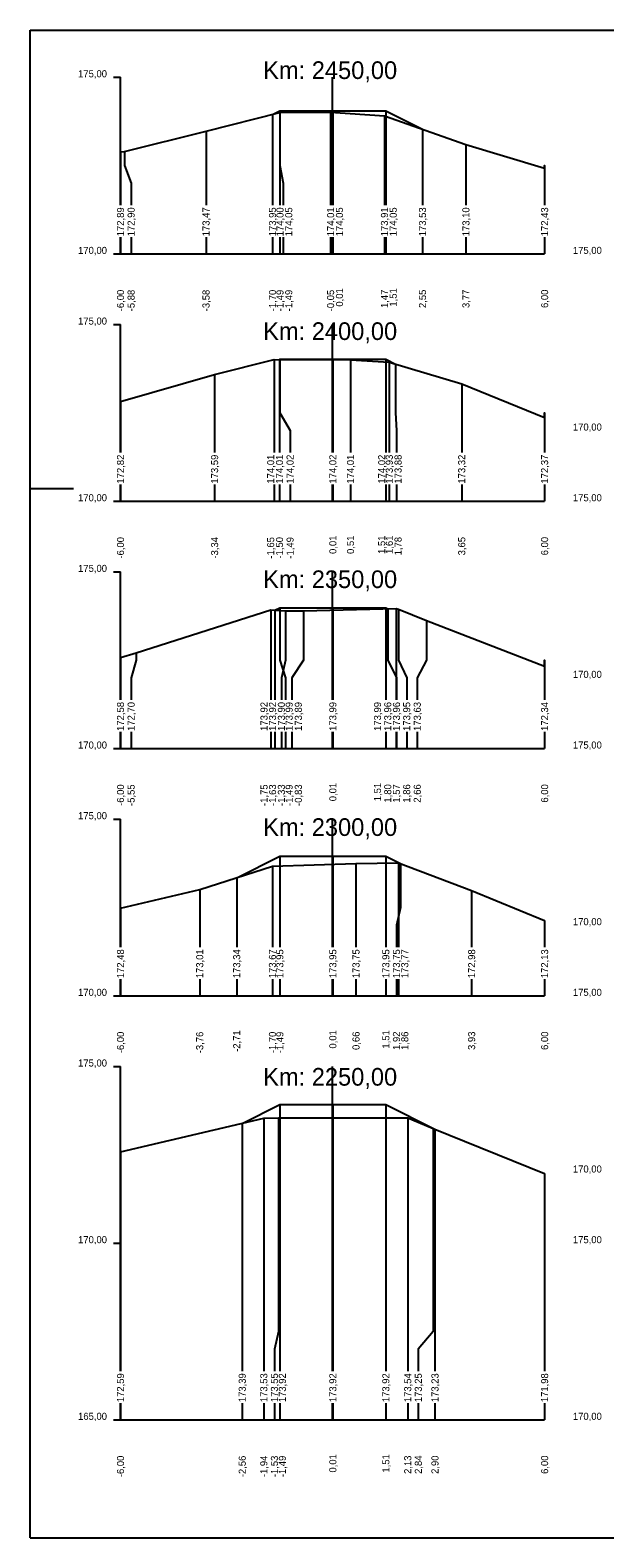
# Model space of a CAD drawing. Extents: x -614174 to -599765, y -1185887 to -1181080.
# Drawn here: x -601090.94 to -601074.69, y -1184533.61 to -1184490.94 of the extents above; entities that cross this region are included whole.
import ezdxf

# ---------------------------------------------------------------- set-up
doc = ezdxf.new("R2010")
doc.units = 0
for name, color, linetype in [('11', 7, 'Continuous'), ('16', 7, 'Continuous'), ('21', 7, 'Continuous'), ('28', 7, 'Continuous'), ('59', 7, 'Continuous'), ('8', 7, 'Continuous'), ('návrh', 7, 'Continuous')]:
    doc.layers.add(name, color=color, linetype=linetype)

msp = doc.modelspace()

# ---------------------------------------------------------------- linework, layer by layer
for points in [[(-601088.389, -1184494.376), (-601088.271, -1184494.371), (-601085.969, -1184493.797), (-601083.876, -1184493.271), (-601082.444, -1184493.262), (-601080.921, -1184493.362), (-601078.615, -1184494.169), (-601076.389, -1184494.844)], [(-601084.088, -1184493.324), (-601084.088, -1184493.324), (-601084.089, -1184493.324)], [(-601084.088, -1184493.324), (-601083.881, -1184493.22), (-601082.381, -1184493.22), (-601080.881, -1184493.22), (-601079.844, -1184493.739)], [(-601083.881, -1184493.22), (-601083.881, -1184493.22), (-601083.881, -1184493.22)], [(-601082.381, -1184493.22), (-601082.381, -1184493.22), (-601082.381, -1184493.22)], [(-601080.881, -1184493.22), (-601080.881, -1184493.22), (-601080.881, -1184493.22)], [(-601088.389, -1184501.448), (-601085.726, -1184500.681), (-601084.043, -1184500.257), (-601081.882, -1184500.263), (-601080.784, -1184500.336), (-601078.735, -1184500.949), (-601076.389, -1184501.899)], [(-601083.891, -1184500.257), (-601083.881, -1184500.252), (-601082.381, -1184500.252), (-601080.881, -1184500.252), (-601080.61, -1184500.387)], [(-601083.891, -1184500.257), (-601083.891, -1184500.257), (-601083.891, -1184500.257)], [(-601083.881, -1184500.252), (-601083.881, -1184500.252), (-601083.881, -1184500.252)], [(-601082.381, -1184500.252), (-601082.381, -1184500.252), (-601082.381, -1184500.252)], [(-601080.881, -1184500.252), (-601080.881, -1184500.252), (-601080.881, -1184500.252)], [(-601088.389, -1184508.694), (-601087.941, -1184508.565), (-601084.137, -1184507.347), (-601083.717, -1184507.374), (-601083.215, -1184507.375), (-601080.592, -1184507.308), (-601080.525, -1184507.324), (-601079.733, -1184507.644), (-601076.389, -1184508.934)], [(-601084.022, -1184507.354), (-601083.881, -1184507.284), (-601082.381, -1184507.284), (-601080.881, -1184507.284), (-601080.821, -1184507.314)], [(-601084.022, -1184507.354), (-601084.022, -1184507.354), (-601084.022, -1184507.354)], [(-601083.881, -1184507.284), (-601083.881, -1184507.284), (-601083.881, -1184507.284)], [(-601082.381, -1184507.284), (-601082.381, -1184507.284), (-601082.381, -1184507.284)], [(-601080.881, -1184507.284), (-601080.881, -1184507.284), (-601080.881, -1184507.284)], [(-601085.101, -1184514.926), (-601083.881, -1184514.316), (-601082.381, -1184514.316), (-601080.881, -1184514.316), (-601080.471, -1184514.521)], [(-601083.881, -1184514.316), (-601083.881, -1184514.316), (-601083.881, -1184514.316)], [(-601082.381, -1184514.316), (-601082.381, -1184514.316), (-601082.381, -1184514.316)], [(-601080.881, -1184514.316), (-601080.881, -1184514.316), (-601080.881, -1184514.316)], [(-601088.389, -1184515.79), (-601086.148, -1184515.26), (-601084.09, -1184514.603), (-601081.726, -1184514.522), (-601080.526, -1184514.5), (-601078.454, -1184515.285), (-601076.389, -1184516.14)], [(-601085.102, -1184514.926), (-601085.101, -1184514.926), (-601085.101, -1184514.925)], [(-601084.944, -1184521.879), (-601083.881, -1184521.348), (-601082.381, -1184521.348), (-601080.881, -1184521.348), (-601079.491, -1184522.043)], [(-601083.881, -1184521.348), (-601083.881, -1184521.348), (-601083.881, -1184521.348)], [(-601082.381, -1184521.348), (-601082.381, -1184521.348), (-601082.381, -1184521.348)], [(-601080.881, -1184521.348), (-601080.881, -1184521.348), (-601080.881, -1184521.348)], [(-601088.389, -1184522.684), (-601084.334, -1184521.736), (-601083.915, -1184521.722), (-601080.262, -1184521.726), (-601079.546, -1184522.021), (-601076.389, -1184523.294)], [(-601084.944, -1184521.879), (-601084.944, -1184521.879), (-601084.944, -1184521.879)]]:
    msp.add_lwpolyline(points)
at = {"layer": '11'}
for points in [[(-601084.088, -1184493.324), (-601084.088, -1184494.77), (-601084.088, -1184495.27), (-601084.088, -1184495.892)], [(-601083.881, -1184493.22), (-601083.881, -1184494.77), (-601083.788, -1184495.27), (-601083.788, -1184495.892)], [(-601083.876, -1184493.271), (-601083.876, -1184494.77), (-601083.876, -1184495.27), (-601083.876, -1184495.892)], [(-601082.444, -1184493.262), (-601082.444, -1184494.77), (-601082.444, -1184495.27), (-601082.444, -1184495.892)], [(-601082.381, -1184493.22), (-601082.381, -1184494.77), (-601082.381, -1184495.27), (-601082.381, -1184495.892)], [(-601080.921, -1184493.362), (-601080.921, -1184494.77), (-601080.921, -1184495.27), (-601080.921, -1184495.892)], [(-601080.881, -1184493.22), (-601080.881, -1184494.77), (-601080.881, -1184495.27), (-601080.881, -1184495.892)], [(-601085.969, -1184493.797), (-601085.969, -1184494.77), (-601085.969, -1184495.27), (-601085.969, -1184495.892)], [(-601079.844, -1184493.739), (-601079.844, -1184494.77), (-601079.844, -1184495.27), (-601079.844, -1184495.892)], [(-601078.615, -1184494.169), (-601078.615, -1184494.77), (-601078.615, -1184495.27), (-601078.615, -1184495.892)], [(-601088.389, -1184494.376), (-601088.389, -1184494.77), (-601088.389, -1184495.27), (-601088.389, -1184495.892)], [(-601088.271, -1184494.371), (-601088.271, -1184494.77), (-601088.089, -1184495.27), (-601088.089, -1184495.892)], [(-601076.389, -1184494.844), (-601076.389, -1184494.77), (-601076.389, -1184495.27), (-601076.389, -1184495.892)], [(-601088.389, -1184496.8), (-601088.389, -1184497.27)], [(-601088.089, -1184496.8), (-601088.089, -1184497.27)], [(-601085.969, -1184496.8), (-601085.969, -1184497.27)], [(-601084.088, -1184496.8), (-601084.088, -1184497.27)], [(-601083.876, -1184496.8), (-601083.876, -1184497.27)], [(-601083.788, -1184496.8), (-601083.788, -1184497.27)], [(-601082.444, -1184496.8), (-601082.444, -1184497.27)], [(-601082.381, -1184496.8), (-601082.381, -1184497.27)], [(-601080.921, -1184496.8), (-601080.921, -1184497.27)], [(-601080.881, -1184496.8), (-601080.881, -1184497.27)], [(-601079.844, -1184496.8), (-601079.844, -1184497.27)], [(-601078.615, -1184496.8), (-601078.615, -1184497.27)], [(-601076.389, -1184496.8), (-601076.389, -1184497.27)], [(-601084.043, -1184500.257), (-601084.043, -1184501.77), (-601084.043, -1184502.27), (-601084.043, -1184502.892)], [(-601083.891, -1184500.257), (-601083.891, -1184501.77), (-601083.891, -1184502.27), (-601083.891, -1184502.892)], [(-601083.881, -1184500.252), (-601083.881, -1184501.77), (-601083.591, -1184502.27), (-601083.591, -1184502.892)], [(-601082.381, -1184500.252), (-601082.381, -1184501.77), (-601082.381, -1184502.27), (-601082.381, -1184502.892)], [(-601081.882, -1184500.263), (-601081.882, -1184501.77), (-601081.882, -1184502.27), (-601081.882, -1184502.892)], [(-601080.881, -1184500.252), (-601080.881, -1184501.77), (-601080.881, -1184502.27), (-601080.881, -1184502.892)], [(-601085.726, -1184500.681), (-601085.726, -1184501.77), (-601085.726, -1184502.27), (-601085.726, -1184502.892)], [(-601080.784, -1184500.336), (-601080.784, -1184501.77), (-601080.784, -1184502.27), (-601080.784, -1184502.892)], [(-601080.61, -1184500.387), (-601080.61, -1184501.77), (-601080.581, -1184502.27), (-601080.581, -1184502.892)], [(-601078.735, -1184500.949), (-601078.735, -1184501.77), (-601078.735, -1184502.27), (-601078.735, -1184502.892)], [(-601088.389, -1184501.448), (-601088.389, -1184501.77), (-601088.389, -1184502.27), (-601088.389, -1184502.892)], [(-601076.389, -1184501.899), (-601076.389, -1184501.77), (-601076.389, -1184502.27), (-601076.389, -1184502.892)], [(-601088.389, -1184503.8), (-601088.389, -1184504.27)], [(-601085.726, -1184503.8), (-601085.726, -1184504.27)], [(-601084.043, -1184503.8), (-601084.043, -1184504.27)], [(-601083.891, -1184503.8), (-601083.891, -1184504.27)], [(-601083.591, -1184503.8), (-601083.591, -1184504.27)], [(-601082.381, -1184503.8), (-601082.381, -1184504.27)], [(-601081.882, -1184503.8), (-601081.882, -1184504.27)], [(-601080.881, -1184503.8), (-601080.881, -1184504.27)], [(-601080.784, -1184503.8), (-601080.784, -1184504.27)], [(-601080.581, -1184503.8), (-601080.581, -1184504.27)], [(-601078.735, -1184503.8), (-601078.735, -1184504.27)], [(-601076.389, -1184503.8), (-601076.389, -1184504.27)], [(-601084.137, -1184507.347), (-601084.137, -1184508.77), (-601084.137, -1184509.27), (-601084.137, -1184509.892)], [(-601084.022, -1184507.354), (-601084.022, -1184508.77), (-601084.022, -1184509.27), (-601084.022, -1184509.892)], [(-601083.881, -1184507.284), (-601083.881, -1184508.77), (-601083.722, -1184509.27), (-601083.722, -1184509.892)], [(-601083.717, -1184507.374), (-601083.717, -1184508.77), (-601083.837, -1184509.27), (-601083.837, -1184509.892)], [(-601083.215, -1184507.375), (-601083.215, -1184508.77), (-601083.537, -1184509.27), (-601083.537, -1184509.892)], [(-601082.381, -1184507.284), (-601082.381, -1184508.77), (-601082.381, -1184509.27), (-601082.381, -1184509.892)], [(-601080.881, -1184507.284), (-601080.881, -1184508.77), (-601080.881, -1184509.27), (-601080.881, -1184509.892)], [(-601080.821, -1184507.314), (-601080.821, -1184508.77), (-601080.581, -1184509.27), (-601080.581, -1184509.892)], [(-601080.592, -1184507.308), (-601080.592, -1184508.77), (-601080.592, -1184509.27), (-601080.592, -1184509.892)], [(-601080.525, -1184507.324), (-601080.525, -1184508.77), (-601080.292, -1184509.27), (-601080.292, -1184509.892)], [(-601079.733, -1184507.644), (-601079.733, -1184508.77), (-601079.992, -1184509.27), (-601079.992, -1184509.892)], [(-601088.389, -1184508.694), (-601088.389, -1184508.77), (-601088.389, -1184509.27), (-601088.389, -1184509.892)], [(-601087.941, -1184508.565), (-601087.941, -1184508.77), (-601088.089, -1184509.27), (-601088.089, -1184509.892)], [(-601076.389, -1184508.934), (-601076.389, -1184508.77), (-601076.389, -1184509.27), (-601076.389, -1184509.892)], [(-601088.389, -1184510.8), (-601088.389, -1184511.27)], [(-601088.089, -1184510.8), (-601088.089, -1184511.27)], [(-601084.137, -1184510.8), (-601084.137, -1184511.27)], [(-601084.022, -1184510.8), (-601084.022, -1184511.27)], [(-601083.837, -1184510.8), (-601083.837, -1184511.27)], [(-601083.722, -1184510.8), (-601083.722, -1184511.27)], [(-601083.537, -1184510.8), (-601083.537, -1184511.27)], [(-601082.381, -1184510.8), (-601082.381, -1184511.27)], [(-601080.881, -1184510.8), (-601080.881, -1184511.27)], [(-601080.592, -1184510.8), (-601080.592, -1184511.27)], [(-601080.581, -1184510.8), (-601080.581, -1184511.27)], [(-601080.292, -1184510.8), (-601080.292, -1184511.27)], [(-601079.992, -1184510.8), (-601079.992, -1184511.27)], [(-601076.389, -1184510.8), (-601076.389, -1184511.27)], [(-601083.881, -1184514.316), (-601083.881, -1184515.77), (-601083.881, -1184516.27), (-601083.881, -1184516.892)], [(-601082.381, -1184514.316), (-601082.381, -1184515.77), (-601082.381, -1184516.27), (-601082.381, -1184516.892)], [(-601080.881, -1184514.316), (-601080.881, -1184515.77), (-601080.881, -1184516.27), (-601080.881, -1184516.892)], [(-601084.09, -1184514.603), (-601084.09, -1184515.77), (-601084.09, -1184516.27), (-601084.09, -1184516.892)], [(-601081.726, -1184514.522), (-601081.726, -1184515.77), (-601081.726, -1184516.27), (-601081.726, -1184516.892)], [(-601080.471, -1184514.521), (-601080.471, -1184515.77), (-601080.581, -1184516.27), (-601080.581, -1184516.892)], [(-601080.526, -1184514.5), (-601080.526, -1184515.77), (-601080.526, -1184516.27), (-601080.526, -1184516.892)], [(-601086.148, -1184515.26), (-601086.148, -1184515.77), (-601086.148, -1184516.27), (-601086.148, -1184516.892)], [(-601085.101, -1184514.926), (-601085.101, -1184515.77), (-601085.101, -1184516.27), (-601085.101, -1184516.892)], [(-601078.454, -1184515.285), (-601078.454, -1184515.77), (-601078.454, -1184516.27), (-601078.454, -1184516.892)], [(-601088.389, -1184515.79), (-601088.389, -1184515.77), (-601088.389, -1184516.27), (-601088.389, -1184516.892)], [(-601076.389, -1184516.14), (-601076.389, -1184516.27), (-601076.389, -1184516.892)], [(-601088.389, -1184517.8), (-601088.389, -1184518.27)], [(-601086.148, -1184517.8), (-601086.148, -1184518.27)], [(-601085.101, -1184517.8), (-601085.101, -1184518.27)], [(-601084.09, -1184517.8), (-601084.09, -1184518.27)], [(-601083.881, -1184517.8), (-601083.881, -1184518.27)], [(-601082.381, -1184517.8), (-601082.381, -1184518.27)], [(-601081.726, -1184517.8), (-601081.726, -1184518.27)], [(-601080.881, -1184517.8), (-601080.881, -1184518.27)], [(-601080.581, -1184517.8), (-601080.581, -1184518.27)], [(-601080.526, -1184517.8), (-601080.526, -1184518.27)], [(-601078.454, -1184517.8), (-601078.454, -1184518.27)], [(-601076.389, -1184517.8), (-601076.389, -1184518.27)], [(-601083.881, -1184521.348), (-601083.881, -1184527.77), (-601083.881, -1184528.27), (-601083.881, -1184528.892)], [(-601082.381, -1184521.348), (-601082.381, -1184527.77), (-601082.381, -1184528.27), (-601082.381, -1184528.892)], [(-601080.881, -1184521.348), (-601080.881, -1184527.77), (-601080.881, -1184528.27), (-601080.881, -1184528.892)], [(-601084.944, -1184521.879), (-601084.944, -1184527.77), (-601084.944, -1184528.27), (-601084.944, -1184528.892)], [(-601084.334, -1184521.736), (-601084.334, -1184527.77), (-601084.334, -1184528.27), (-601084.334, -1184528.892)], [(-601083.915, -1184521.722), (-601083.915, -1184527.77), (-601084.034, -1184528.27), (-601084.034, -1184528.892)], [(-601080.262, -1184521.726), (-601080.262, -1184527.77), (-601080.262, -1184528.27), (-601080.262, -1184528.892)], [(-601079.546, -1184522.021), (-601079.546, -1184527.77), (-601079.962, -1184528.27), (-601079.962, -1184528.892)], [(-601079.491, -1184522.043), (-601079.491, -1184527.77), (-601079.491, -1184528.27), (-601079.491, -1184528.892)], [(-601088.389, -1184522.684), (-601088.389, -1184527.77), (-601088.389, -1184528.27), (-601088.389, -1184528.892)], [(-601076.389, -1184523.294), (-601076.389, -1184527.77), (-601076.389, -1184528.27), (-601076.389, -1184528.892)], [(-601088.389, -1184529.8), (-601088.389, -1184530.27)], [(-601084.944, -1184529.8), (-601084.944, -1184530.27)], [(-601084.334, -1184529.8), (-601084.334, -1184530.27)], [(-601084.034, -1184529.8), (-601084.034, -1184530.27)], [(-601083.881, -1184529.8), (-601083.881, -1184530.27)], [(-601082.381, -1184529.8), (-601082.381, -1184530.27)], [(-601080.881, -1184529.8), (-601080.881, -1184530.27)], [(-601080.262, -1184529.8), (-601080.262, -1184530.27)], [(-601079.962, -1184529.8), (-601079.962, -1184530.27)], [(-601079.491, -1184529.8), (-601079.491, -1184530.27)], [(-601076.389, -1184529.8), (-601076.389, -1184530.27)]]:
    msp.add_lwpolyline(points, dxfattribs=at)
at = {"layer": '16'}
for p, q in [((-601088.389, -1184497.27), (-601076.389, -1184497.27)), ((-601088.389, -1184504.27), (-601076.389, -1184504.27)), ((-601088.389, -1184511.27), (-601076.389, -1184511.27)), ((-601088.389, -1184518.27), (-601076.389, -1184518.27)), ((-601088.389, -1184530.27), (-601076.389, -1184530.27))]:
    msp.add_line(p, q, dxfattribs=at)
for points in [[(-601079.843, -1184493.739), (-601079.844, -1184493.739), (-601079.844, -1184493.739)], [(-601080.611, -1184500.387), (-601080.61, -1184500.387), (-601080.61, -1184500.388)], [(-601080.821, -1184507.314), (-601080.821, -1184507.314), (-601080.821, -1184507.314)], [(-601080.471, -1184514.521), (-601080.471, -1184514.521), (-601080.471, -1184514.521)], [(-601079.491, -1184522.043), (-601079.491, -1184522.043), (-601079.491, -1184522.043)]]:
    msp.add_lwpolyline(points, dxfattribs=at)
at = {"layer": '21'}
for p, q in [((-601088.589, -1184492.27), (-601088.389, -1184492.27)), ((-601088.589, -1184497.27), (-601088.389, -1184497.27)), ((-601088.589, -1184499.27), (-601088.389, -1184499.27)), ((-601088.589, -1184504.27), (-601088.389, -1184504.27)), ((-601088.589, -1184506.27), (-601088.389, -1184506.27)), ((-601088.589, -1184511.27), (-601088.389, -1184511.27)), ((-601088.589, -1184513.27), (-601088.389, -1184513.27)), ((-601088.589, -1184518.27), (-601088.389, -1184518.27)), ((-601088.589, -1184520.27), (-601088.389, -1184520.27)), ((-601088.589, -1184525.27), (-601088.389, -1184525.27)), ((-601088.589, -1184530.27), (-601088.389, -1184530.27))]:
    msp.add_line(p, q, dxfattribs=at)
at = {"layer": '28'}
for p, q in [((-601082.389, -1184495.892), (-601082.389, -1184492.27)), ((-601082.389, -1184497.27), (-601082.389, -1184496.8)), ((-601082.389, -1184502.892), (-601082.389, -1184499.27)), ((-601082.389, -1184504.27), (-601082.389, -1184503.8)), ((-601082.389, -1184509.892), (-601082.389, -1184506.27)), ((-601082.389, -1184511.27), (-601082.389, -1184510.8)), ((-601082.389, -1184516.892), (-601082.389, -1184513.27)), ((-601082.389, -1184518.27), (-601082.389, -1184517.8)), ((-601082.389, -1184528.892), (-601082.389, -1184520.27)), ((-601082.389, -1184530.27), (-601082.389, -1184529.8))]:
    msp.add_line(p, q, dxfattribs=at)
at = {"layer": '8'}
for p, q in [((-601088.389, -1184495.892), (-601088.389, -1184492.27)), ((-601088.389, -1184497.27), (-601088.389, -1184496.8)), ((-601088.389, -1184502.892), (-601088.389, -1184499.27)), ((-601088.389, -1184504.27), (-601088.389, -1184503.8)), ((-601088.389, -1184509.892), (-601088.389, -1184506.27)), ((-601088.389, -1184511.27), (-601088.389, -1184510.8)), ((-601088.389, -1184516.892), (-601088.389, -1184513.27)), ((-601088.389, -1184518.27), (-601088.389, -1184517.8)), ((-601088.389, -1184528.892), (-601088.389, -1184520.27)), ((-601088.389, -1184530.27), (-601088.389, -1184529.8))]:
    msp.add_line(p, q, dxfattribs=at)
at = {"layer": 'návrh'}
for p, q in [((-601090.944, -1184503.91), (-601090.944, -1184490.936)), ((-601090.944, -1184490.936), (-600943.944, -1184490.936)), ((-601090.944, -1184533.61), (-601090.944, -1184503.91)), ((-601090.944, -1184503.91), (-601089.717, -1184503.91)), ((-601090.944, -1184533.61), (-601069.944, -1184533.61))]:
    msp.add_line(p, q, dxfattribs=at)

# ---------------------------------------------------------------- texts
at = {"layer": '16'}
for s, p in [('172,89', (-601088.289, -1184496.77)), ('172,90', (-601087.989, -1184496.77)), ('173,47', (-601085.869, -1184496.77)), ('173,95', (-601083.988, -1184496.77)), ('174,00', (-601083.776, -1184496.77)), ('174,05', (-601083.529, -1184496.77)), ('174,01', (-601082.344, -1184496.77)), ('174,05', (-601082.094, -1184496.77)), ('173,91', (-601080.821, -1184496.77)), ('174,05', (-601080.573, -1184496.77)), ('173,53', (-601079.744, -1184496.77)), ('173,10', (-601078.515, -1184496.77)), ('172,43', (-601076.289, -1184496.77)), ('172,82', (-601088.289, -1184503.77)), ('173,59', (-601085.626, -1184503.77)), ('174,01', (-601084.04, -1184503.77)), ('174,01', (-601083.791, -1184503.77)), ('174,02', (-601083.491, -1184503.77)), ('174,02', (-601082.281, -1184503.77)), ('174,01', (-601081.782, -1184503.77)), ('174,02', (-601080.899, -1184503.77)), ('173,93', (-601080.684, -1184503.77)), ('173,88', (-601080.436, -1184503.77)), ('173,32', (-601078.635, -1184503.77)), ('172,37', (-601076.289, -1184503.77)), ('172,58', (-601088.289, -1184510.77)), ('172,70', (-601087.989, -1184510.77)), ('173,92', (-601084.228, -1184510.77)), ('173,92', (-601083.988, -1184510.77)), ('173,90', (-601083.737, -1184510.77)), ('173,99', (-601083.518, -1184510.77)), ('173,89', (-601083.257, -1184510.77)), ('173,99', (-601082.281, -1184510.77)), ('173,99', (-601081.017, -1184510.77)), ('173,96', (-601080.728, -1184510.77)), ('173,96', (-601080.481, -1184510.77)), ('173,95', (-601080.192, -1184510.77)), ('173,63', (-601079.892, -1184510.77)), ('172,34', (-601076.289, -1184510.77)), ('172,48', (-601088.289, -1184517.77)), ('173,01', (-601086.048, -1184517.77)), ('173,34', (-601085.001, -1184517.77)), ('173,67', (-601083.99, -1184517.77)), ('173,95', (-601083.781, -1184517.77)), ('173,95', (-601082.281, -1184517.77)), ('173,75', (-601081.626, -1184517.77)), ('173,95', (-601080.781, -1184517.77)), ('173,75', (-601080.481, -1184517.77)), ('173,77', (-601080.246, -1184517.77)), ('172,98', (-601078.354, -1184517.77)), ('172,13', (-601076.289, -1184517.77)), ('172,59', (-601088.289, -1184529.77)), ('173,39', (-601084.844, -1184529.77)), ('173,53', (-601084.234, -1184529.77)), ('173,55', (-601083.934, -1184529.77)), ('173,92', (-601083.709, -1184529.77)), ('173,92', (-601082.281, -1184529.77)), ('173,92', (-601080.781, -1184529.77)), ('173,54', (-601080.162, -1184529.77)), ('173,25', (-601079.862, -1184529.77)), ('173,23', (-601079.391, -1184529.77)), ('171,98', (-601076.289, -1184529.77))]:
    msp.add_text(s, height=0.2, rotation=90, dxfattribs=at).set_placement(p)
at = {"layer": '21'}
for s, p in [('175,00', (-601089.589, -1184492.27)), ('170,00', (-601089.589, -1184497.27)), ('175,00', (-601075.589, -1184497.27)), ('175,00', (-601089.589, -1184499.27)), ('170,00', (-601075.589, -1184502.27)), ('170,00', (-601089.589, -1184504.27)), ('175,00', (-601075.589, -1184504.27)), ('175,00', (-601089.589, -1184506.27)), ('170,00', (-601075.589, -1184509.27)), ('170,00', (-601089.589, -1184511.27)), ('175,00', (-601075.589, -1184511.27)), ('175,00', (-601089.589, -1184513.27)), ('170,00', (-601075.589, -1184516.27)), ('170,00', (-601089.589, -1184518.27)), ('175,00', (-601075.589, -1184518.27)), ('175,00', (-601089.589, -1184520.27)), ('170,00', (-601075.589, -1184523.27)), ('170,00', (-601089.589, -1184525.27)), ('175,00', (-601075.589, -1184525.27)), ('165,00', (-601089.589, -1184530.27)), ('170,00', (-601075.589, -1184530.27))]:
    msp.add_text(s, height=0.2, dxfattribs=at).set_placement(p)
at = {"layer": '28'}
for s, p in [('Km: 2450,00', (-601084.352, -1184492.319)), ('Km: 2400,00', (-601084.352, -1184499.706)), ('Km: 2350,00', (-601084.352, -1184506.728)), ('Km: 2300,00', (-601084.352, -1184513.743)), ('Km: 2250,00', (-601084.352, -1184520.811))]:
    msp.add_text(s, height=0.5, dxfattribs=at).set_placement(p)
at = {"layer": '59'}
for s, p in [('-6,00', (-601088.289, -1184498.893)), ('-5,88', (-601087.989, -1184498.894)), ('-3,58', (-601085.869, -1184498.894)), ('-1,70', (-601083.988, -1184498.893)), ('-1,49', (-601083.776, -1184498.894)), ('-1,49', (-601083.529, -1184498.894)), ('-0,05', (-601082.344, -1184498.895)), ('0,01', (-601082.094, -1184498.762)), ('1,47', (-601080.821, -1184498.801)), ('1,51', (-601080.573, -1184498.762)), ('2,55', (-601079.744, -1184498.802)), ('3,77', (-601078.515, -1184498.801)), ('6,00', (-601076.289, -1184498.8)), ('-6,00', (-601088.289, -1184505.893)), ('-3,34', (-601085.626, -1184505.893)), ('-1,65', (-601084.04, -1184505.895)), ('-1,50', (-601083.791, -1184505.893)), ('-1,49', (-601083.491, -1184505.894)), ('0,01', (-601082.281, -1184505.762)), ('0,51', (-601081.782, -1184505.762)), ('1,51', (-601080.899, -1184505.762)), ('1,61', (-601080.684, -1184505.762)), ('1,78', (-601080.436, -1184505.801)), ('3,65', (-601078.635, -1184505.802)), ('6,00', (-601076.289, -1184505.8)), ('0,01', (-601082.281, -1184512.762)), ('1,51', (-601081.017, -1184512.762)), ('-6,00', (-601088.289, -1184512.893)), ('-5,55', (-601087.989, -1184512.895)), ('-1,75', (-601084.228, -1184512.895)), ('-1,63', (-601083.988, -1184512.894)), ('-1,33', (-601083.737, -1184512.894)), ('-1,49', (-601083.518, -1184512.894)), ('-0,83', (-601083.257, -1184512.894)), ('1,80', (-601080.728, -1184512.8)), ('1,57', (-601080.481, -1184512.801)), ('1,86', (-601080.192, -1184512.801)), ('2,66', (-601079.892, -1184512.801)), ('6,00', (-601076.289, -1184512.8)), ('-6,00', (-601088.289, -1184519.893)), ('-3,76', (-601086.048, -1184519.894)), ('-2,71', (-601085.001, -1184519.855)), ('-1,70', (-601083.99, -1184519.893)), ('-1,49', (-601083.781, -1184519.894)), ('0,01', (-601082.281, -1184519.762)), ('0,66', (-601081.626, -1184519.801)), ('1,51', (-601080.781, -1184519.762)), ('1,92', (-601080.481, -1184519.799)), ('1,86', (-601080.246, -1184519.801)), ('3,93', (-601078.354, -1184519.801)), ('6,00', (-601076.289, -1184519.8)), ('-6,00', (-601088.289, -1184531.893)), ('-2,56', (-601084.844, -1184531.894)), ('-1,94', (-601084.234, -1184531.893)), ('-1,53', (-601083.934, -1184531.894)), ('-1,49', (-601083.709, -1184531.894)), ('0,01', (-601082.281, -1184531.762)), ('1,51', (-601080.781, -1184531.762)), ('2,13', (-601080.162, -1184531.801)), ('2,84', (-601079.862, -1184531.8)), ('2,90', (-601079.391, -1184531.8)), ('6,00', (-601076.289, -1184531.8))]:
    msp.add_text(s, height=0.2, rotation=90, dxfattribs=at).set_placement(p)

doc.saveas('drawing.dxf')
